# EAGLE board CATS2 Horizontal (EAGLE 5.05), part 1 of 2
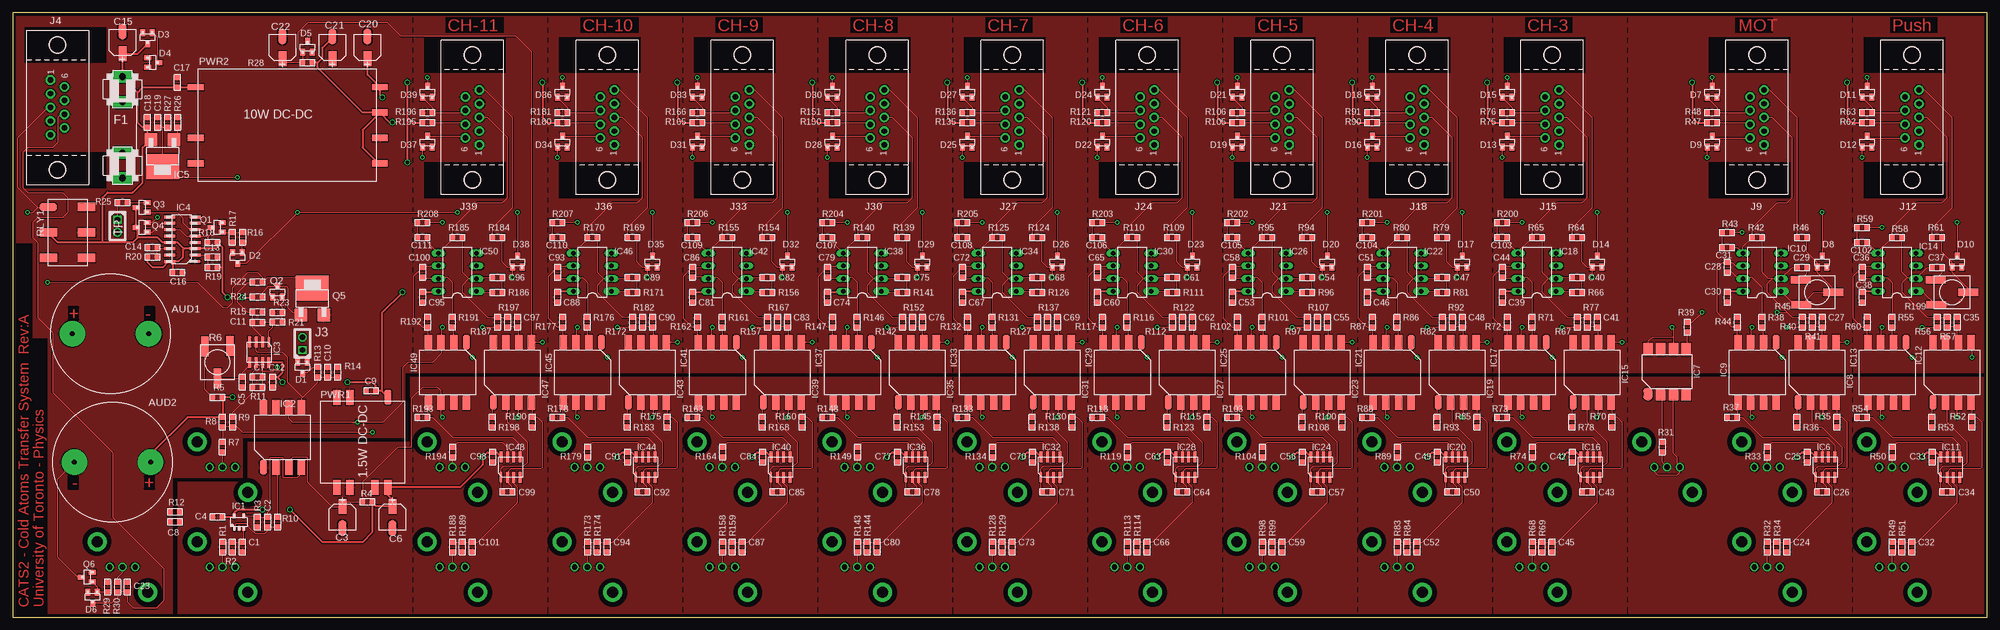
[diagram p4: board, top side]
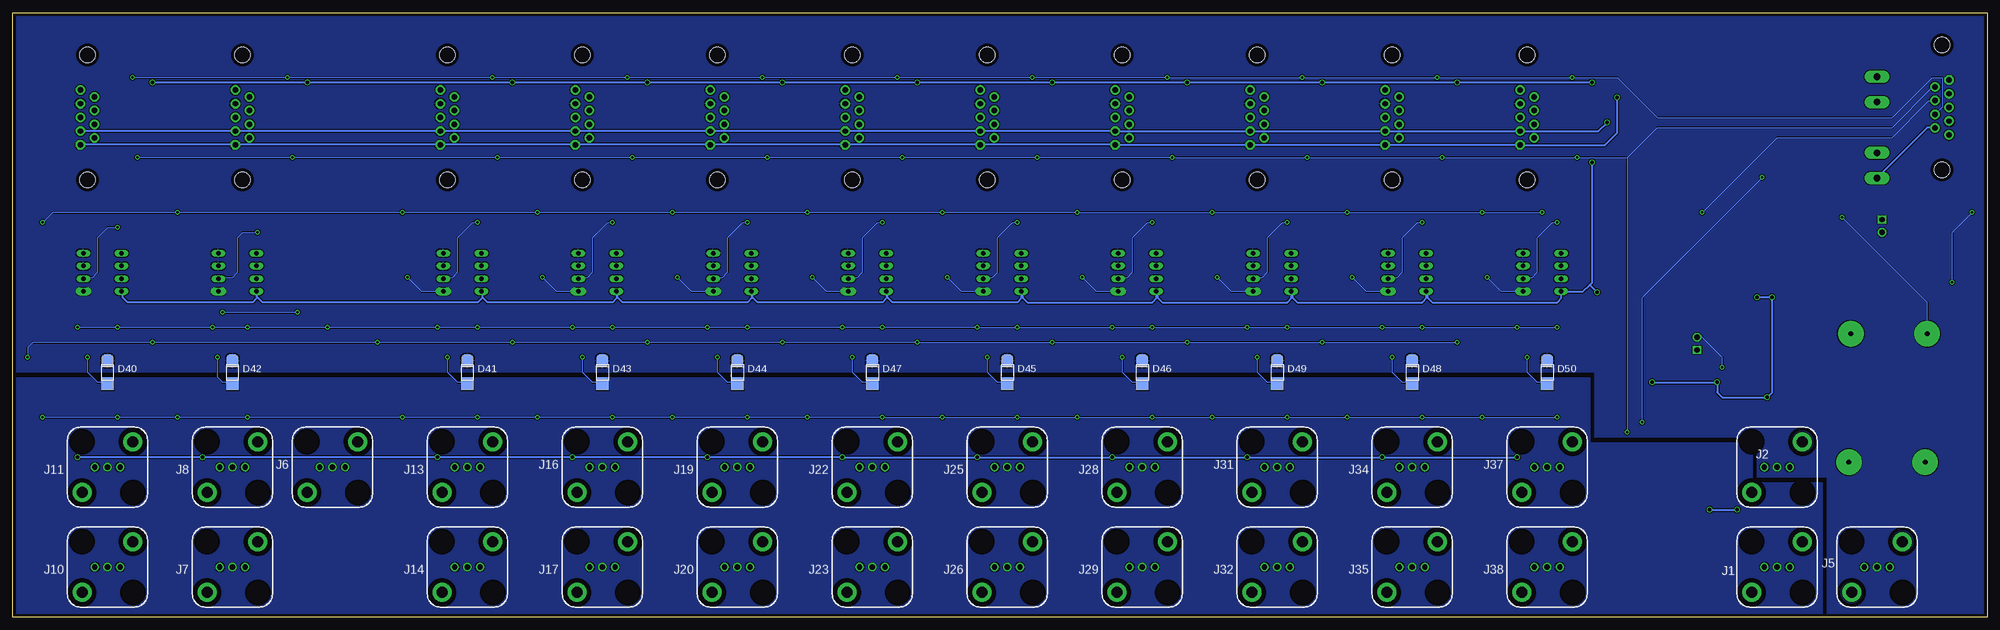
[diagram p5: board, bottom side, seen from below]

Size 395 x 121 mm. Coordinates in mm from the lower left corner, seen from the top.
Outline: 0,0 395,0 395,121 0,121 0,0
Copper layers (1+16): Top 0.035mm / dielectric 1.5mm / Bottom 0.035mm
Design rules "DRC standard check *": minimum track width 7mil, minimum drill 20mil, track to track 7mil, track to pad 7mil, pad to pad 7mil, via to via 7mil, smd to smd 0mil, copper to edge 25mil, drill to drill 8mil, minimum pad ring 10mil, minimum via ring 8mil, stop-mask expansion 4mil, vias tented up to drill 0mil, thermal gap 10mil
Net classes: 1 Power: width 0.381 mm, drill 0.711 mm
tRestrict: 693 lines

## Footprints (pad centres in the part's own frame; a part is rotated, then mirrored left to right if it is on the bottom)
MALLORY_MSR = drill 0.965 pad 5.08 round: + -7.62,0; - 7.62,0
2012(0805) = smd 1.016 x 1.397: 1 -0.953,0; 2 0.953,0
CAP:NIPPONCHEM_E61 = smd 3 x 1.6: NEG -2.2,0; POS 2.2,0
SOT23 = smd 1 x 1.4: 1 -0.953,-0.953; 2 0.953,-0.953; 3 0,1.27
1209 = smd 2.5 x 2.5: A 2.3,0; K -2.3,0
FUSE = drill 1.321 pad 2.54 long: 1A -10.16,0; 1B -5.08,0; 2A 10.16,0; 2B 5.08,0
SOT23-5 = smd 0.635 x 0.991: 1 -0.635,-1.27; 2 0.318,-1.27; 3 1.27,-1.27; 4 1.27,1.27; 5 -0.635,1.27
SMD:AVAGO#300(8PIN) = smd 1.5 x 3: 1 -3.81,-6; 2 -1.27,-6; 3 1.27,-6; 4 3.81,-6; 5 3.81,6; 6 1.27,6; 7 -1.27,6; 8 -3.81,6
SOIC-8 = smd 0.6 x 2.2: 1 -1.27,-2.032; 2 0,-2.032; 3 1.27,-2.032; 4 2.54,-2.032; 5 2.54,2.032; 6 1.27,2.032; 7 0,2.032; 8 -1.27,2.032
SOIC-16 = smd 0.6 x 2.2: 1 -3.81,-2.54; 2 -2.54,-2.54; 3 -1.27,-2.54; 4 0,-2.54; 5 1.27,-2.54; 6 2.54,-2.54; 7 3.81,-2.54; 8 5.08,-2.54; 9 5.08,2.54; 10 3.81,2.54; 11 2.54,2.54; 12 1.27,2.54; 13 0,2.54; 14 -1.27,2.54; 15 -2.54,2.54; 16 -3.81,2.54
SOT223(C) = smd 2.54 x 2.54: 1 -2.286,-2.54; 3 2.286,-2.54 | smd 6.6 x 5: 2 -0.05,2.87
SMD:6N13X(8PIN) = smd 1.905 x 2.54: 1 -3.81,-4.508; 2 -1.27,-4.508; 3 1.27,-4.508; 4 3.81,-4.508; 5 3.81,4.508; 6 1.27,4.508; 7 -1.27,4.508; 8 -3.81,4.508
DIL08 = drill 0.889 pad 1.575 long: 1 -3.81,-3.81 | drill 0.889 long: 2 -1.27,-3.81; 3 1.27,-3.81; 4 3.81,-3.81; 5 3.81,3.81; 6 1.27,3.81; 7 -1.27,3.81; 8 -3.81,3.81
CONN-BNC-AMP-TYPE1VERT = drill 1.067 round: CONDUCTOR 0,0; SHIELD1 -2.54,0; SHIELD2 2.54,0 | drill 2.184 pad 3.81 round: MTG1 -5.08,-5.08; MTG2 5.08,5.08
JUMPER-1X2 = drill 1.067 square: 1 0,2.54 | drill 1.067 octagon: 2 0,0
CONN-DB9-H/V1 = drill 1.067 pad 1.905 octagon: 1 -5.48,-1.42 | drill 1.067 pad 1.905 round: 2 -2.74,-1.42; 3 0,-1.42; 4 2.74,-1.42; 5 5.48,-1.42; 6 -4.11,1.42; 7 -1.37,1.42; 8 1.37,1.42; 9 4.11,1.42 | hole 3.175: -12.5,0; 12.5,0
DC-DC:CC1R5-XXXXX-R-E(TDK/LAMBDA) = smd 3 x 1.5: +VIN -9,5.1; +VOUT 9,5.08; -VIN -9,-5.08; -VOUT 9,-5.08; COM 9,-2.54; RC -9,-2.54; TRM 9,2.54
DC-DC:CC10-XXXXX-R-E(TDK/LAMBDA) = smd 3.175 x 1.27: +VIN -17.78,7.62; +VOUT 19.05,7.62; -VIN -17.78,-7.62; -VOUT 19.05,-7.62; COM 19.05,-2.54; RC -17.78,-2.54; TRM 19.05,2.54
BOURNS_3361P = smd 1.5 x 4: CCW -2.54,-3.3; CW 2.54,-3.2; W 0,3.2
RELAY:SPDT-TYCO_V23026 = smd 1.75 x 3.5: 1 -5.08,-3.81; 3 0,-3.81; 5 5.08,-3.81; 6 5.08,3.81; 8 0,3.81; 10 -5.08,3.81

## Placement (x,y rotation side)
AUD1  MSR320R  [MALLORY_MSR]  19.6,56.7 0 top
AUD2  MSR516W  [MALLORY_MSR]  20,31 180 top
C1  1nF  [2012(0805)]  46,14 90 top
C2  100pF  [2012(0805)]  51,19 270 top
C3  39uF  [CAP:NIPPONCHEM_E61]  66,20 90 top
C4  0.1uF  [2012(0805)]  41,20 180 top
C5  0.1uF  [2012(0805)]  46,47 90 top
C6  39uF  [CAP:NIPPONCHEM_E61]  76,20 90 top
C7  1nF  [2012(0805)]  49,48 180 top
C8  0.1uF  [2012(0805)]  32.5,19 180 top
C9  0.1uF  [2012(0805)]  71.74,45.24 180 top
C10  100pF  [2012(0805)]  63,49 270 top
C11  1nF  [2012(0805)]  49,59 0 top
C12  0.1uF  [2012(0805)]  52,47 270 top
C13  3.3uF  [2012(0805)]  40,72 180 top
C14  0.1uF  [2012(0805)]  28,74 0 top
C15  39uF  [CAP:NIPPONCHEM_E61]  22,115 270 top
C16  0.1uF  [2012(0805)]  33,69 0 top
C17  0.1uF  [2012(0805)]  33,107 90 top
C18  0.1uF  [2012(0805)]  27,99 90 top
C19  0.1uF  [2012(0805)]  29,99 270 top
C20  39uF  [CAP:NIPPONCHEM_E61]  71,114 270 top
C21  39uF  [CAP:NIPPONCHEM_E61]  64,114 270 top
C22  39uF  [CAP:NIPPONCHEM_E61]  54,114 270 top
C23  0.1uF  [2012(0805)]  23,6 90 top
C24  1nF  [2012(0805)]  355,14 90 top
C25  0.1uF  [2012(0805)]  359,32 270 top
C26  100pF  [2012(0805)]  362,25 180 top
C27  100pF  [2012(0805)]  362,59 270 top
C28  27pF  [2012(0805)]  343,70 270 top
C29  10nF  [2012(0805)]  358,70 0 top
C30  0.1uF  [2012(0805)]  343,64 270 top
C31  ???  [2012(0805)]  343,74 0 top
C32  1nF  [2012(0805)]  380,14 90 top
C33  0.1uF  [2012(0805)]  384,32 270 top
C34  100pF  [2012(0805)]  387,25 180 top
C35  100pF  [2012(0805)]  389,59 270 top
C36  27pF  [2012(0805)]  370,69 270 top
C37  10nF  [2012(0805)]  385,70 0 top
C38  0.1uF  [2012(0805)]  370,64 270 top
C39  0.1uF  [2012(0805)]  298,64 270 top
C40  10nF  [2012(0805)]  313,68 0 top
C41  100pF  [2012(0805)]  317,59 270 top
C42  0.1uF  [2012(0805)]  312,32 270 top
C43  100pF  [2012(0805)]  315,25 180 top
C44  27pF  [2012(0805)]  298,69 270 top
C45  1nF  [2012(0805)]  308,14 90 top
C46  0.1uF  [2012(0805)]  271,64 270 top
C47  10nF  [2012(0805)]  286,68 0 top
C48  100pF  [2012(0805)]  290,59 270 top
C49  0.1uF  [2012(0805)]  285,32 270 top
C50  100pF  [2012(0805)]  288,25 180 top
C51  27pF  [2012(0805)]  271,69 270 top
C52  1nF  [2012(0805)]  281,14 90 top
C53  0.1uF  [2012(0805)]  244,64 270 top
C54  10nF  [2012(0805)]  259,68 0 top
C55  100pF  [2012(0805)]  263,59 270 top
C56  0.1uF  [2012(0805)]  258,32 270 top
C57  100pF  [2012(0805)]  261,25 180 top
C58  27pF  [2012(0805)]  244,69 270 top
C59  1nF  [2012(0805)]  254,14 90 top
C60  0.1uF  [2012(0805)]  217,64 270 top
C61  10nF  [2012(0805)]  232,68 0 top
C62  100pF  [2012(0805)]  236,59 270 top
C63  0.1uF  [2012(0805)]  231,32 270 top
C64  100pF  [2012(0805)]  234,25 180 top
C65  27pF  [2012(0805)]  217,69 270 top
C66  1nF  [2012(0805)]  227,14 90 top
C67  0.1uF  [2012(0805)]  190,64 270 top
C68  10nF  [2012(0805)]  205,68 0 top
C69  100pF  [2012(0805)]  209,59 270 top
C70  0.1uF  [2012(0805)]  204,32 270 top
C71  100pF  [2012(0805)]  207,25 180 top
C72  27pF  [2012(0805)]  190,69 270 top
C73  1nF  [2012(0805)]  200,14 90 top
C74  0.1uF  [2012(0805)]  163,64 270 top
C75  10nF  [2012(0805)]  178,68 0 top
C76  100pF  [2012(0805)]  182,59 270 top
C77  0.1uF  [2012(0805)]  177,32 270 top
C78  100pF  [2012(0805)]  180,25 180 top
C79  27pF  [2012(0805)]  163,69 270 top
C80  1nF  [2012(0805)]  173,14 90 top
C81  0.1uF  [2012(0805)]  136,64 270 top
C82  10nF  [2012(0805)]  151,68 0 top
C83  100pF  [2012(0805)]  155,59 270 top
C84  0.1uF  [2012(0805)]  150,32 270 top
C85  100pF  [2012(0805)]  153,25 180 top
C86  27pF  [2012(0805)]  136,69 270 top
C87  1nF  [2012(0805)]  146,14 90 top
C88  0.1uF  [2012(0805)]  109,64 270 top
C89  10nF  [2012(0805)]  124,68 0 top
C90  100pF  [2012(0805)]  128,59 270 top
C91  0.1uF  [2012(0805)]  123,32 270 top
C92  100pF  [2012(0805)]  126,25 180 top
C93  27pF  [2012(0805)]  109,69 270 top
C94  1nF  [2012(0805)]  119,14 90 top
C95  0.1uF  [2012(0805)]  82,64 270 top
C96  10nF  [2012(0805)]  97,68 0 top
C97  100pF  [2012(0805)]  101,59 270 top
C98  0.1uF  [2012(0805)]  96,32 270 top
C99  100pF  [2012(0805)]  99,25 180 top
C100  27pF  [2012(0805)]  82,69 270 top
C101  1nF  [2012(0805)]  92,14 90 top
C102  ???  [2012(0805)]  370,75 0 top
C103  ???  [2012(0805)]  298,76 0 top
C104  ???  [2012(0805)]  271,76 0 top
C105  ???  [2012(0805)]  244,76 0 top
C106  ???  [2012(0805)]  217,76 0 top
C107  ???  [2012(0805)]  163,76 0 top
C108  ???  [2012(0805)]  190,76 0 top
C109  ???  [2012(0805)]  136,76 0 top
C110  ???  [2012(0805)]  109,76 0 top
C111  ???  [2012(0805)]  82,76 0 top
D1  BAS21  [SOT23]  58,50 180 top
D2  MMBZ5237BW-7-F  [SOT23]  45,72 180 top
D3  MMBZ5237BW-7-F  [SOT23]  27,116 180 top
D4  MMBZ5237BW-7-F  [SOT23]  28,111 270 top
D5  MMBZ5237BW-7-F  [SOT23]  59,114 0 top
D6  MMBZ5237BW-7-F  [SOT23]  16,4 180 top
D7  BAS21  [SOT23]  340,105 0 top
D8  BAS21  [SOT23]  362,71 0 top
D9  BAS21  [SOT23]  340,95 0 top
D10  BAS21  [SOT23]  389,71 0 top
D11  BAS21  [SOT23]  371,105 0 top
D12  BAS21  [SOT23]  371,95 0 top
D13  BAS21  [SOT23]  299,95 0 top
D14  BAS21  [SOT23]  317,71 0 top
D15  BAS21  [SOT23]  299,105 0 top
D16  BAS21  [SOT23]  272,95 0 top
D17  BAS21  [SOT23]  290,71 0 top
D18  BAS21  [SOT23]  272,105 0 top
D19  BAS21  [SOT23]  245,95 0 top
D20  BAS21  [SOT23]  263,71 0 top
D21  BAS21  [SOT23]  245,105 0 top
D22  BAS21  [SOT23]  218,95 0 top
D23  BAS21  [SOT23]  236,71 0 top
D24  BAS21  [SOT23]  218,105 0 top
D25  BAS21  [SOT23]  191,95 0 top
D26  BAS21  [SOT23]  209,71 0 top
D27  BAS21  [SOT23]  191,105 0 top
D28  BAS21  [SOT23]  164,95 0 top
D29  BAS21  [SOT23]  182,71 0 top
D30  BAS21  [SOT23]  164,105 0 top
D31  BAS21  [SOT23]  137,95 0 top
D32  BAS21  [SOT23]  155,71 0 top
D33  BAS21  [SOT23]  137,105 0 top
D34  BAS21  [SOT23]  110,95 0 top
D35  BAS21  [SOT23]  128,71 0 top
D36  BAS21  [SOT23]  110,105 0 top
D37  BAS21  [SOT23]  83,95 0 top
D38  BAS21  [SOT23]  101,71 0 top
D39  BAS21  [SOT23]  83,105 0 top
D40  SML-LXL1209UPGC  [1209]  376,49 270 bottom
D41  SML-LXL1209UPGC  [1209]  304,49 270 bottom
D42  SML-LXL1209UPGC  [1209]  351,49 270 bottom
D43  SML-LXL1209UPGC  [1209]  277,49 270 bottom
D44  SML-LXL1209UPGC  [1209]  250,49 270 bottom
D45  SML-LXL1209UPGC  [1209]  196,49 270 bottom
D46  SML-LXL1209UPGC  [1209]  169,49 270 bottom
D47  SML-LXL1209UPGC  [1209]  223,49 270 bottom
D48  SML-LXL1209UPGC  [1209]  115,49 270 bottom
D49  SML-LXL1209UPGC  [1209]  142,49 270 bottom
D50  SML-LXL1209UPGC  [1209]  88,49 270 bottom
F1  0.25A  [FUSE]  22,98 270 top
IC1  AD8638ARJZ  [SOT23-5]  45,19 0 top
IC2  HCNR201#500  [SMD:AVAGO#300(8PIN)]  54,36 0 top
IC3  AD823AR  [SOIC-8]  50,53 180 top
IC4  CD4538BCMX  [SOIC-16]  34,75 90 top
IC5  LT3080EST  [SOT223(C)]  30,93 180 top
IC6  AD823AR  [SOIC-8]  362,30 0 top
IC7  6N136S  [SMD:6N13X(8PIN)]  330.99,49.12 0 top
IC8  HCNR201#500  [SMD:AVAGO#300(8PIN)]  361,49 0 top
IC9  HCNR201#500  [SMD:AVAGO#300(8PIN)]  349,49 180 top
IC10  AD823AN  [DIL08]  350,69 90 top
IC11  AD823AR  [SOIC-8]  387,30 0 top
IC12  HCNR201#500  [SMD:AVAGO#300(8PIN)]  388,49 0 top
IC13  HCNR201#500  [SMD:AVAGO#300(8PIN)]  375,49 180 top
IC14  AD823AN  [DIL08]  377,69 90 top
IC15  HCNR201#500  [SMD:AVAGO#300(8PIN)]  316,49 0 top
IC16  AD823AR  [SOIC-8]  315,30 0 top
IC17  HCNR201#500  [SMD:AVAGO#300(8PIN)]  303,49 180 top
IC18  AD823AN  [DIL08]  305,69 90 top
IC19  HCNR201#500  [SMD:AVAGO#300(8PIN)]  289,49 0 top
IC20  AD823AR  [SOIC-8]  288,30 0 top
IC21  HCNR201#500  [SMD:AVAGO#300(8PIN)]  276,49 180 top
IC22  AD823AN  [DIL08]  278,69 90 top
IC23  HCNR201#500  [SMD:AVAGO#300(8PIN)]  262,49 0 top
IC24  AD823AR  [SOIC-8]  261,30 0 top
IC25  HCNR201#500  [SMD:AVAGO#300(8PIN)]  249,49 180 top
IC26  AD823AN  [DIL08]  251,69 90 top
IC27  HCNR201#500  [SMD:AVAGO#300(8PIN)]  235,49 0 top
IC28  AD823AR  [SOIC-8]  234,30 0 top
IC29  HCNR201#500  [SMD:AVAGO#300(8PIN)]  222,49 180 top
IC30  AD823AN  [DIL08]  224,69 90 top
IC31  HCNR201#500  [SMD:AVAGO#300(8PIN)]  208,49 0 top
IC32  AD823AR  [SOIC-8]  207,30 0 top
IC33  HCNR201#500  [SMD:AVAGO#300(8PIN)]  195,49 180 top
IC34  AD823AN  [DIL08]  197,69 90 top
IC35  HCNR201#500  [SMD:AVAGO#300(8PIN)]  181,49 0 top
IC36  AD823AR  [SOIC-8]  180,30 0 top
IC37  HCNR201#500  [SMD:AVAGO#300(8PIN)]  168,49 180 top
IC38  AD823AN  [DIL08]  170,69 90 top
IC39  HCNR201#500  [SMD:AVAGO#300(8PIN)]  154,49 0 top
IC40  AD823AR  [SOIC-8]  153,30 0 top
IC41  HCNR201#500  [SMD:AVAGO#300(8PIN)]  141,49 180 top
IC42  AD823AN  [DIL08]  143,69 90 top
IC43  HCNR201#500  [SMD:AVAGO#300(8PIN)]  127,49 0 top
IC44  AD823AR  [SOIC-8]  126,30 0 top
IC45  HCNR201#500  [SMD:AVAGO#300(8PIN)]  114,49 180 top
IC46  AD823AN  [DIL08]  116,69 90 top
IC47  HCNR201#500  [SMD:AVAGO#300(8PIN)]  100,49 0 top
IC48  AD823AR  [SOIC-8]  99,30 0 top
IC49  HCNR201#500  [SMD:AVAGO#300(8PIN)]  87,49 180 top
IC50  AD823AN  [DIL08]  89,69 90 top
J1  5227222-6  [CONN-BNC-AMP-TYPE1VERT]  42,10 0 bottom
J2  5227222-6  [CONN-BNC-AMP-TYPE1VERT]  42,30 0 bottom
J3  [JUMPER-1X2]  58,56 180 top
J4  1-5747871-4  [CONN-DB9-H/V1]  9,102 270 top
J5  5227222-6  [CONN-BNC-AMP-TYPE1VERT]  22,10 180 bottom
J6  5227222-6  [CONN-BNC-AMP-TYPE1VERT]  331,30 0 bottom
J7  5227222-6  [CONN-BNC-AMP-TYPE1VERT]  351,10 0 bottom
J8  5227222-6  [CONN-BNC-AMP-TYPE1VERT]  351,30 0 bottom
J9  5747150-8  [CONN-DB9-H/V1]  349,100 90 top
J10  5227222-6  [CONN-BNC-AMP-TYPE1VERT]  376,10 0 bottom
J11  5227222-6  [CONN-BNC-AMP-TYPE1VERT]  376,30 0 bottom
J12  5747150-8  [CONN-DB9-H/V1]  380,100 90 top
J13  5227222-6  [CONN-BNC-AMP-TYPE1VERT]  304,30 0 bottom
J14  5227222-6  [CONN-BNC-AMP-TYPE1VERT]  304,10 0 bottom
J15  5747150-8  [CONN-DB9-H/V1]  308,100 90 top
J16  5227222-6  [CONN-BNC-AMP-TYPE1VERT]  277,30 0 bottom
J17  5227222-6  [CONN-BNC-AMP-TYPE1VERT]  277,10 0 bottom
J18  5747150-8  [CONN-DB9-H/V1]  281,100 90 top
J19  5227222-6  [CONN-BNC-AMP-TYPE1VERT]  250,30 0 bottom
J20  5227222-6  [CONN-BNC-AMP-TYPE1VERT]  250,10 0 bottom
J21  5747150-8  [CONN-DB9-H/V1]  254,100 90 top
J22  5227222-6  [CONN-BNC-AMP-TYPE1VERT]  223,30 0 bottom
J23  5227222-6  [CONN-BNC-AMP-TYPE1VERT]  223,10 0 bottom
J24  5747150-8  [CONN-DB9-H/V1]  227,100 90 top
J25  5227222-6  [CONN-BNC-AMP-TYPE1VERT]  196,30 0 bottom
J26  5227222-6  [CONN-BNC-AMP-TYPE1VERT]  196,10 0 bottom
J27  5747150-8  [CONN-DB9-H/V1]  200,100 90 top
J28  5227222-6  [CONN-BNC-AMP-TYPE1VERT]  169,30 0 bottom
J29  5227222-6  [CONN-BNC-AMP-TYPE1VERT]  169,10 0 bottom
J30  5747150-8  [CONN-DB9-H/V1]  173,100 90 top
J31  5227222-6  [CONN-BNC-AMP-TYPE1VERT]  142,30 0 bottom
J32  5227222-6  [CONN-BNC-AMP-TYPE1VERT]  142,10 0 bottom
J33  5747150-8  [CONN-DB9-H/V1]  146,100 90 top
J34  5227222-6  [CONN-BNC-AMP-TYPE1VERT]  115,30 0 bottom
J35  5227222-6  [CONN-BNC-AMP-TYPE1VERT]  115,10 0 bottom
J36  5747150-8  [CONN-DB9-H/V1]  119,100 90 top
J37  5227222-6  [CONN-BNC-AMP-TYPE1VERT]  88,30 0 bottom
J38  5227222-6  [CONN-BNC-AMP-TYPE1VERT]  88,10 0 bottom
J39  5747150-8  [CONN-DB9-H/V1]  92,100 90 top
PWR1  CC1R5-1212SF-E  [DC-DC:CC1R5-XXXXX-R-E(TDK/LAMBDA)]  70,35 270 top
PWR2  CC10-1212DR-E  [DC-DC:CC10-XXXXX-R-E(TDK/LAMBDA)]  54.45,98.43 0 top
Q1  MMBT5551  [SOT23]  41,78 90 top
Q2  MMBT5551  [SOT23]  53,65 0 top
Q3  MMBT5551  [SOT23]  26,82 90 top
Q4  MMBT5551  [SOT23]  26,78 90 top
Q5  IRFM120A  [SOT223(C)]  60,63 0 top
Q6  MMBT5551  [SOT23]  15,8 90 top
R1  10K  [2012(0805)]  42,14 270 top
R2  10K  [2012(0805)]  44,14 90 top
R3  100K  [2012(0805)]  49,19 90 top
R4  200  [2012(0805)]  71,23 180 top
R5  90.9K  [2012(0805)]  41,44 0 top
R6  10K  [BOURNS_3361P]  41,51 180 top
R7  1K  [2012(0805)]  42,34 90 top
R8  10K  [2012(0805)]  42,39 90 top
R9  10K  [2012(0805)]  44,39 270 top
R10  1K  [2012(0805)]  53,19 270 top
R11  100K  [2012(0805)]  49,46 0 top
R12  100K  [2012(0805)]  32.5,21 180 top
R13  100K  [2012(0805)]  61,49 270 top
R14  80.6K  [2012(0805)]  65,49 270 top
R15  10K  [2012(0805)]  49,61 180 top
R16  1K  [2012(0805)]  46,76 270 top
R17  10K  [2012(0805)]  44,76 90 top
R18  10K  [2012(0805)]  40,75 0 top
R19  1M  [2012(0805)]  40,70 0 top
R20  1M  [2012(0805)]  28,72 180 top
R21  10K  [2012(0805)]  53,59 180 top
R22  90.9K  [2012(0805)]  49,67 180 top
R23  10K  [2012(0805)]  53,61 0 top
R24  1K  [2012(0805)]  49,64 180 top
R25  1K  [2012(0805)]  22,83 0 top
R26  499K  [2012(0805)]  33,99 270 top
R27  4.99K  [2012(0805)]  31,99 270 top
R28  1K  [2012(0805)]  59,111 0 top
R29  80.6K  [2012(0805)]  19,6 270 top
R30  1K  [2012(0805)]  21,6 270 top
R31  200  [2012(0805)]  330,34 270 top
R32  10K  [2012(0805)]  351,14 270 top
R33  1K  [2012(0805)]  351,33 270 top
R34  10K  [2012(0805)]  353,14 90 top
R35  100K  [2012(0805)]  365,39 90 top
R36  1K  [2012(0805)]  357,39 90 top
R37  200K  [2012(0805)]  344,40 0 top
R38  1K  [2012(0805)]  350,59 90 top
R39  10K  [2012(0805)]  335,58 270 top
R40  3.3M  [2012(0805)]  358,59 270 top
R41  80.6K  [2012(0805)]  360,59 270 top
R42  10K  [2012(0805)]  349,76 0 top
R43  ???  [2012(0805)]  343,77 0 top
R44  80.6K  [2012(0805)]  345,59 270 top
R45  500K  [BOURNS_3361P]  361,65 270 top
R46  100  [2012(0805)]  358,76 0 top
R47  200  [2012(0805)]  340,99 0 top
R48  4.99K  [2012(0805)]  340,101 0 top
R49  10K  [2012(0805)]  376,14 270 top
R50  1K  [2012(0805)]  376,33 270 top
R51  10K  [2012(0805)]  378,14 90 top
R52  100K  [2012(0805)]  392,39 90 top
R53  1K  [2012(0805)]  384,39 90 top
R54  200K  [2012(0805)]  370,40 0 top
R55  1K  [2012(0805)]  376,59 90 top
R56  3.3M  [2012(0805)]  385,59 270 top
R57  80.6K  [2012(0805)]  387,59 270 top
R58  10K  [2012(0805)]  377,76 0 top
R59  ???  [2012(0805)]  370,78 0 top
R60  80.6K  [2012(0805)]  371,59 270 top
R61  100  [2012(0805)]  385,76 0 top
R62  200  [2012(0805)]  371,99 0 top
R63  4.99K  [2012(0805)]  371,101 0 top
R64  100  [2012(0805)]  313,76 0 top
R65  10K  [2012(0805)]  305,76 0 top
R66  200K  [2012(0805)]  313,65 0 top
R67  3.3M  [2012(0805)]  313,59 270 top
R68  10K  [2012(0805)]  304,14 270 top
R69  10K  [2012(0805)]  306,14 90 top
R70  100K  [2012(0805)]  320,39 90 top
R71  1K  [2012(0805)]  304,59 90 top
R72  80.6K  [2012(0805)]  299,59 270 top
R73  200K  [2012(0805)]  298,40 0 top
R74  1K  [2012(0805)]  304,33 270 top
R75  200  [2012(0805)]  299,99 0 top
R76  4.99K  [2012(0805)]  299,101 0 top
R77  80.6K  [2012(0805)]  315,59 270 top
R78  1K  [2012(0805)]  312,39 90 top
R79  100  [2012(0805)]  286,76 0 top
R80  10K  [2012(0805)]  278,76 0 top
R81  200K  [2012(0805)]  286,65 0 top
R82  3.3M  [2012(0805)]  286,59 270 top
R83  10K  [2012(0805)]  277,14 270 top
R84  10K  [2012(0805)]  279,14 90 top
R85  100K  [2012(0805)]  293,39 90 top
R86  1K  [2012(0805)]  277,59 90 top
R87  80.6K  [2012(0805)]  272,59 270 top
R88  200K  [2012(0805)]  271,40 0 top
R89  1K  [2012(0805)]  277,33 270 top
R90  200  [2012(0805)]  272,99 0 top
R91  4.99K  [2012(0805)]  272,101 0 top
R92  80.6K  [2012(0805)]  288,59 270 top
R93  1K  [2012(0805)]  285,39 90 top
R94  100  [2012(0805)]  259,76 0 top
R95  10K  [2012(0805)]  251,76 0 top
R96  200K  [2012(0805)]  259,65 0 top
R97  3.3M  [2012(0805)]  259,59 270 top
R98  10K  [2012(0805)]  250,14 270 top
R99  10K  [2012(0805)]  252,14 90 top
R100  100K  [2012(0805)]  266,39 90 top
R101  1K  [2012(0805)]  250,59 90 top
R102  80.6K  [2012(0805)]  245,59 270 top
R103  200K  [2012(0805)]  244,40 0 top
R104  1K  [2012(0805)]  250,33 270 top
R105  200  [2012(0805)]  245,99 0 top
R106  4.99K  [2012(0805)]  245,101 0 top
R107  80.6K  [2012(0805)]  261,59 270 top
R108  1K  [2012(0805)]  258,39 90 top
R109  100  [2012(0805)]  232,76 0 top
R110  10K  [2012(0805)]  224,76 0 top
R111  200K  [2012(0805)]  232,65 0 top
R112  3.3M  [2012(0805)]  232,59 270 top
R113  10K  [2012(0805)]  223,14 270 top
R114  10K  [2012(0805)]  225,14 90 top
R115  100K  [2012(0805)]  239,39 90 top
R116  1K  [2012(0805)]  223,59 90 top
R117  80.6K  [2012(0805)]  218,59 270 top
R118  200K  [2012(0805)]  217,40 0 top
R119  1K  [2012(0805)]  223,33 270 top
R120  200  [2012(0805)]  218,99 0 top
R121  4.99K  [2012(0805)]  218,101 0 top
R122  80.6K  [2012(0805)]  234,59 270 top
R123  1K  [2012(0805)]  231,39 90 top
R124  100  [2012(0805)]  205,76 0 top
R125  10K  [2012(0805)]  197,76 0 top
R126  200K  [2012(0805)]  205,65 0 top
R127  3.3M  [2012(0805)]  205,59 270 top
R128  10K  [2012(0805)]  196,14 270 top
R129  10K  [2012(0805)]  198,14 90 top
R130  100K  [2012(0805)]  212,39 90 top
R131  1K  [2012(0805)]  196,59 90 top
R132  80.6K  [2012(0805)]  191,59 270 top
R133  200K  [2012(0805)]  190,40 0 top
R134  1K  [2012(0805)]  196,33 270 top
R135  200  [2012(0805)]  191,99 0 top
R136  4.99K  [2012(0805)]  191,101 0 top
R137  80.6K  [2012(0805)]  207,59 270 top
R138  1K  [2012(0805)]  204,39 90 top
R139  100  [2012(0805)]  178,76 0 top
R140  10K  [2012(0805)]  170,76 0 top
R141  200K  [2012(0805)]  178,65 0 top
R142  3.3M  [2012(0805)]  178,59 270 top
R143  10K  [2012(0805)]  169,14 270 top
R144  10K  [2012(0805)]  171,14 90 top
R145  100K  [2012(0805)]  185,39 90 top
R146  1K  [2012(0805)]  169,59 90 top
R147  80.6K  [2012(0805)]  164,59 270 top
R148  200K  [2012(0805)]  163,40 0 top
R149  1K  [2012(0805)]  169,33 270 top
R150  200  [2012(0805)]  164,99 0 top
R151  4.99K  [2012(0805)]  164,101 0 top
R152  80.6K  [2012(0805)]  180,59 270 top
R153  1K  [2012(0805)]  177,39 90 top
R154  100  [2012(0805)]  151,76 0 top
R155  10K  [2012(0805)]  143,76 0 top
R156  200K  [2012(0805)]  151,65 0 top
R157  3.3M  [2012(0805)]  151,59 270 top
R158  10K  [2012(0805)]  142,14 270 top
R159  10K  [2012(0805)]  144,14 90 top
R160  100K  [2012(0805)]  158,39 90 top
R161  1K  [2012(0805)]  142,59 90 top
R162  80.6K  [2012(0805)]  137,59 270 top
R163  200K  [2012(0805)]  136,40 0 top
R164  1K  [2012(0805)]  142,33 270 top
R165  200  [2012(0805)]  137,99 0 top
R166  4.99K  [2012(0805)]  137,101 0 top
R167  80.6K  [2012(0805)]  153,59 270 top
R168  1K  [2012(0805)]  150,39 90 top
R169  100  [2012(0805)]  124,76 0 top
R170  10K  [2012(0805)]  116,76 0 top
R171  200K  [2012(0805)]  124,65 0 top
R172  3.3M  [2012(0805)]  124,59 270 top
R173  10K  [2012(0805)]  115,14 270 top
R174  10K  [2012(0805)]  117,14 90 top
R175  100K  [2012(0805)]  131,39 90 top
R176  1K  [2012(0805)]  115,59 90 top
R177  80.6K  [2012(0805)]  110,59 270 top
R178  200K  [2012(0805)]  109,40 0 top
R179  1K  [2012(0805)]  115,33 270 top
R180  200  [2012(0805)]  110,99 0 top
R181  4.99K  [2012(0805)]  110,101 0 top
R182  80.6K  [2012(0805)]  126,59 270 top
R183  1K  [2012(0805)]  123,39 90 top
R184  100  [2012(0805)]  97,76 0 top
R185  10K  [2012(0805)]  89,76 0 top
R186  200K  [2012(0805)]  97,65 0 top
R187  3.3M  [2012(0805)]  97,59 270 top
R188  10K  [2012(0805)]  88,14 270 top
R189  10K  [2012(0805)]  90,14 90 top
R190  100K  [2012(0805)]  104,39 90 top
R191  1K  [2012(0805)]  88,59 90 top
R192  80.6K  [2012(0805)]  83,59 270 top
R193  200K  [2012(0805)]  82,40 0 top
R194  1K  [2012(0805)]  88,33 270 top
R195  200  [2012(0805)]  83,99 0 top
R196  4.99K  [2012(0805)]  83,101 0 top
R197  80.6K  [2012(0805)]  99,59 270 top
R198  1K  [2012(0805)]  96,39 90 top
R199  500K  [BOURNS_3361P]  388,65 270 top
R200  ???  [2012(0805)]  298,79 0 top
R201  ???  [2012(0805)]  271,79 0 top
R202  ???  [2012(0805)]  244,79 0 top
R203  ???  [2012(0805)]  217,79 0 top
R204  ???  [2012(0805)]  163,79 0 top
R205  ???  [2012(0805)]  190,79 0 top
R206  ???  [2012(0805)]  136,79 0 top
R207  ???  [2012(0805)]  109,79 0 top
R208  ???  [2012(0805)]  82,79 0 top
RLY1  V23026D1022B201  [RELAY:SPDT-TYCO_V23026]  11,77 270 top
TP  [JUMPER-1X2]  21,77 0 top
U$279  [TITLEBLOCK_PCB]  296,-3 0 top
